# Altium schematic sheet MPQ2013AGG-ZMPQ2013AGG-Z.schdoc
size 127 x 101 mm
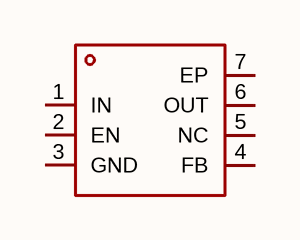
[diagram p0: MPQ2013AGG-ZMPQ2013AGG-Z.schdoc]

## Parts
U?  mpq2013agg-z  [QFN-6_L2.0-W2.0-P0.65--MPQ2013AGG-Z]  (value not drawn)

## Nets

Not connected (* = marked no-connect by the designer): U? 1(IN) 2(EN) 3(GND) 4(FB) 5(NC) 6(OUT) 7(EP)

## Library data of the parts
U? = mpq2013agg-z: 输出类型:可调;工作电压:40V;输出电压:1.215V~15V;输出电流:150mA;输出极性:正极;; Manufacturer: MPS(芯源); AddInBom: yes; Output Type: 可调; Voltage - Supply: 40V; Output Current: 150mA; Voltage Dropout: 600mV; standby current: 3.3uA; Output Configuration: 正极; Number of Outputs: 1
